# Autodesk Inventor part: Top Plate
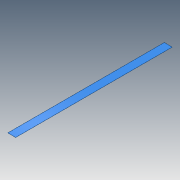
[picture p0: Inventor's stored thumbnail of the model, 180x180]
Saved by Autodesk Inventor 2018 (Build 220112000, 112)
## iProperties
Created: 2018-02
Part Number: Top Plate
Material: Steel, Mild
Document SubType Name: Modeling
Designer: STK
Density: 7.85 g/cm^3
Appearance: Cyan
Author: STK
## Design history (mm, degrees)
sketch "Sketch1"
  geometry: L1 (190.5, 3778.25)-(-190.5, 3778.25); L2 (-190.5, 3778.25)-(-190.5, -3778.25); L3 (-190.5, -3778.25)-(190.5, -3778.25); L4 (190.5, -3778.25)-(190.5, 3778.25); L5 (190.5, 3778.25)-(-190.5, -3778.25); L6 (-190.5, 3778.25)-(190.5, -3778.25); 1 further point
  constraints: 12 end point, 2 midpoint, 2 parallel, 1 horizontal, 1 perpendicular
  dimensions: "d0" = 381 distance of L3.end L2.end; "d1" = 7556.5 distance of L2.end L1.end
extrude "Extrusion1" new body sketch "Sketch1" distance "d2" = 6.35; taper "d3" = 0 deg
body "Solid1"
